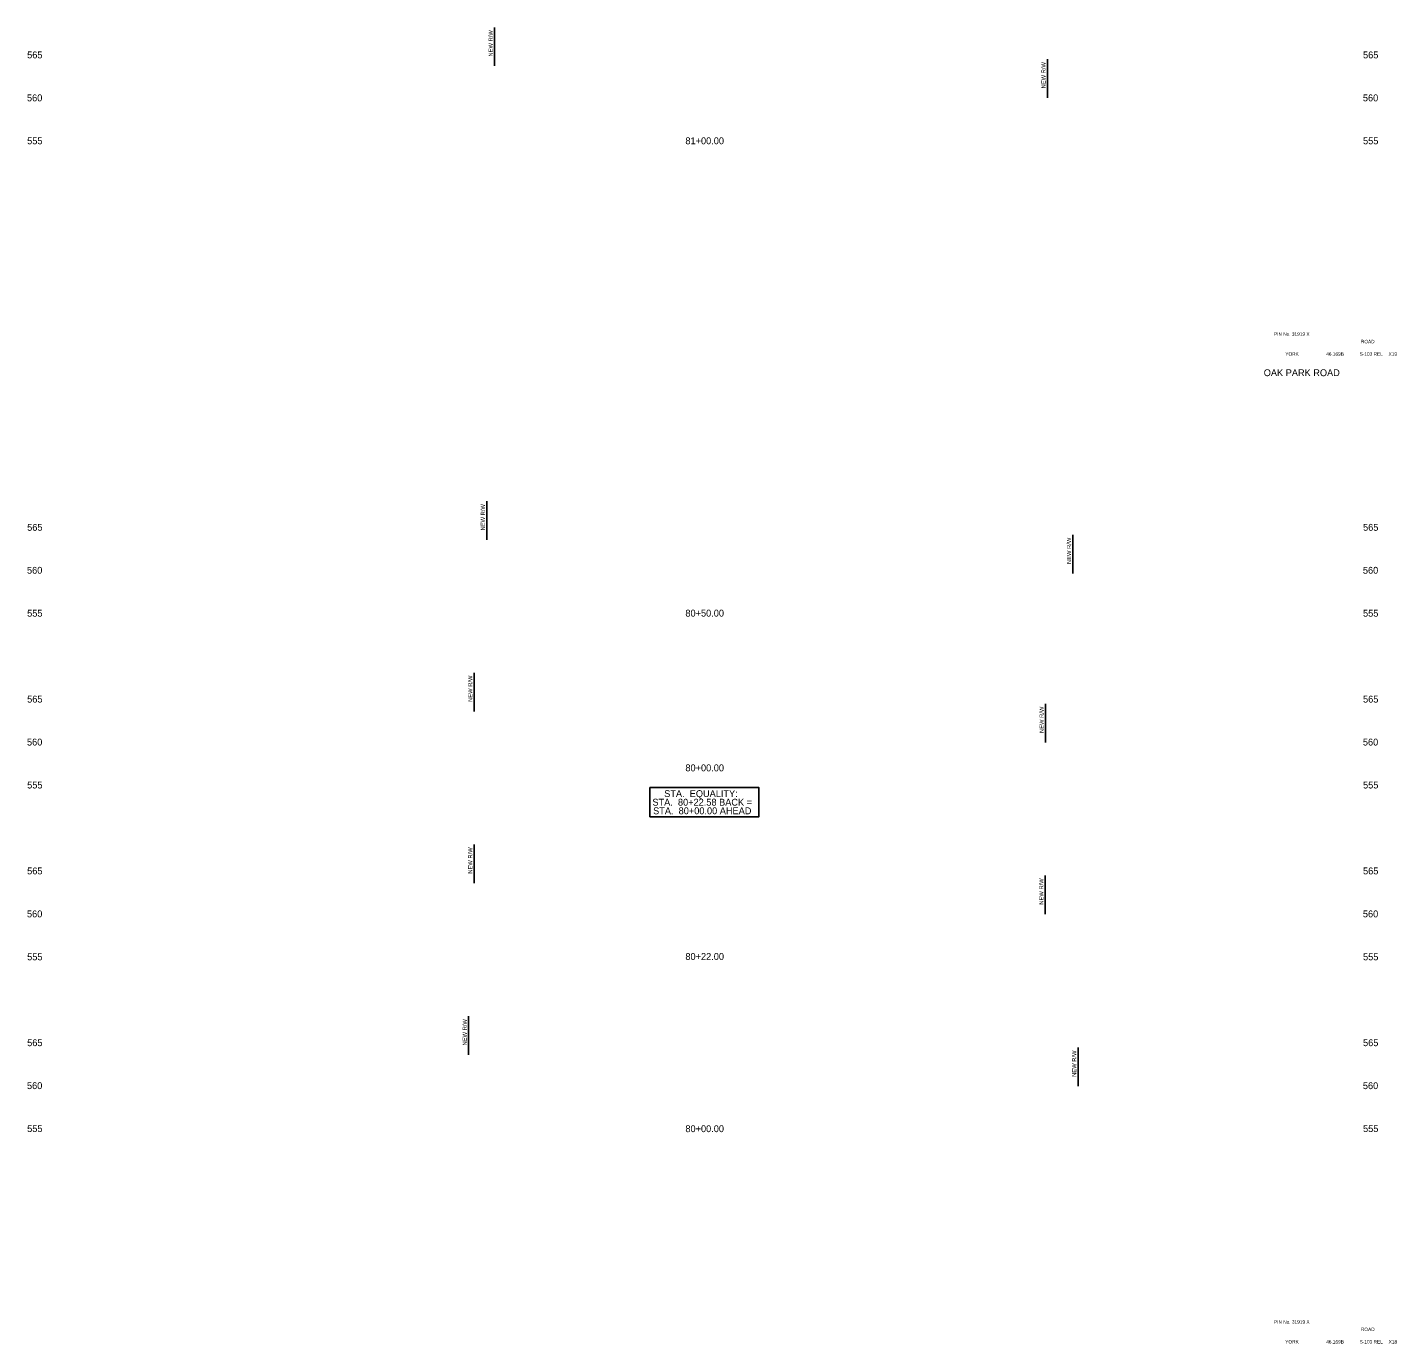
# Model space of a CAD drawing. Extents: x 1001 to 1161, y 1005 to 3518.
# Drawn here: x 1001.2 to 1160.6, y 3055.5 to 3208.7 of the extents above; entities that cross this region are included whole.
import ezdxf

# ---------------------------------------------------------------- set-up
doc = ezdxf.new("R2010")
doc.units = 0
for name, color, linetype in [('RD_SHT_TX', 7, 'Continuous'), ('RD_XS_NewRW', 7, 'Continuous'), ('RD_XS_TX_Elev_EX', 7, 'Continuous'), ('RD_XS_TX_Misc', 7, 'Continuous'), ('RD_XS_TX_Station', 7, 'Continuous')]:
    doc.layers.add(name, color=color, linetype=linetype)

msp = doc.modelspace()

# ---------------------------------------------------------------- linework, layer by layer
at = {"layer": 'RD_XS_NewRW'}
for p, q in [((1055.56, 3208.71), (1055.56, 3204.21)), ((1119.91, 3205), (1119.91, 3200.5)), ((1054.65, 3153.54), (1054.65, 3149.04)), ((1122.88, 3149.63), (1122.88, 3145.13)), ((1053.19, 3133.57), (1053.19, 3129.07)), ((1119.7, 3129.96), (1119.7, 3125.46)), ((1053.18, 3113.57), (1053.18, 3109.07)), ((1119.66, 3109.97), (1119.66, 3105.47)), ((1052.54, 3093.58), (1052.54, 3089.08)), ((1123.48, 3089.93), (1123.48, 3085.43))]:
    msp.add_line(p, q, dxfattribs=at)
at = {"layer": 'RD_XS_TX_Misc'}
msp.add_lwpolyline([(1073.65, 3120.2), (1086.34, 3120.2), (1086.34, 3116.8), (1073.65, 3116.8)], close=True, dxfattribs=at)

# ---------------------------------------------------------------- texts
at = {"layer": 'RD_SHT_TX'}
for s, height, p in [('PIN No. 31919 X', 0.4, (1146.29, 3172.8)), ('ROAD', 0.4, (1156.41, 3171.93)), ('YORK', 0.4, (1147.61, 3170.48)), ('46.169B', 0.4, (1152.37, 3170.48)), ('S-103 REL', 0.4, (1156.26, 3170.48)), ('X19', 0.4, (1159.63, 3170.48)), ('OAK PARK ROAD', 0.8, (1145.1, 3168.1)), ('PIN No. 31919 X', 0.4, (1146.29, 3057.8)), ('ROAD', 0.4, (1156.41, 3056.93)), ('YORK', 0.4, (1147.61, 3055.48)), ('46.169B', 0.4, (1152.37, 3055.48)), ('S-103 REL', 0.4, (1156.26, 3055.48)), ('X18', 0.4, (1159.64, 3055.48))]:
    msp.add_text(s, height=height, dxfattribs=at).set_placement(p)
at = {"layer": 'RD_XS_NewRW'}
for p in [(1055.36, 3205.31), (1119.71, 3201.6), (1054.45, 3150.14), (1122.68, 3146.23), (1052.99, 3130.18), (1119.5, 3126.56), (1052.98, 3110.18), (1119.46, 3106.57), (1052.34, 3090.18), (1123.28, 3086.53)]:
    msp.add_text('NEW R/W ', height=0.488, rotation=90, dxfattribs=at).set_placement(p)
at = {"layer": 'RD_XS_TX_Elev_EX'}
for s, p in [('565', (1001.16, 3205.1)), ('565', (1156.66, 3205.1)), ('560', (1001.14, 3200.1)), ('560', (1156.64, 3200.1)), ('555', (1001.16, 3195.1)), ('555', (1156.66, 3195.1)), ('565', (1001.16, 3150.1)), ('565', (1156.66, 3150.1)), ('560', (1001.14, 3145.1)), ('560', (1156.64, 3145.1)), ('555', (1001.16, 3140.1)), ('555', (1156.66, 3140.1)), ('565', (1001.16, 3130.1)), ('565', (1156.66, 3130.1)), ('560', (1001.14, 3125.1)), ('560', (1156.64, 3125.1)), ('555', (1001.16, 3120.1)), ('555', (1156.66, 3120.1)), ('565', (1001.16, 3110.1)), ('565', (1156.66, 3110.1)), ('560', (1001.14, 3105.1)), ('560', (1156.64, 3105.1)), ('555', (1001.16, 3100.1)), ('555', (1156.66, 3100.1)), ('565', (1001.16, 3090.1)), ('565', (1156.66, 3090.1)), ('560', (1001.14, 3085.1)), ('560', (1156.64, 3085.1)), ('555', (1001.16, 3080.1)), ('555', (1156.66, 3080.1))]:
    msp.add_text(s, height=0.8, dxfattribs=at).set_placement(p)
at = {"layer": 'RD_XS_TX_Misc'}
for s, p in [('STA.  EQUALITY:', (1075.31, 3119.1)), ('STA.  80+22.58 BACK =', (1073.94, 3118.1)), ('STA.  80+00.00 AHEAD', (1074.02, 3117.1))]:
    msp.add_text(s, height=0.8, dxfattribs=at).set_placement(p)
at = {"layer": 'RD_XS_TX_Station'}
for s, p in [('81+00.00', (1077.78, 3195.1)), ('80+50.00', (1077.78, 3140.11)), ('80+00.00', (1077.78, 3122.1)), ('80+22.00', (1077.78, 3100.14)), ('80+00.00', (1077.78, 3080.09))]:
    msp.add_text(s, height=0.8, dxfattribs=at).set_placement(p)

doc.saveas('drawing.dxf')
